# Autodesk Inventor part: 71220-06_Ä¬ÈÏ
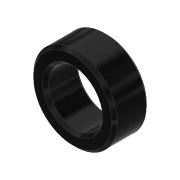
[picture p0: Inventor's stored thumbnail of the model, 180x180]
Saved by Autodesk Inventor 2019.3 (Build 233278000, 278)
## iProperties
Created: 2010-06
Part Number: 71220-06_Ä¬ÈÏ
Material: Ogólny
Document SubType Name: Modeling
Designer: CADENGINEERING4
Density: 1 g/cm^3
Appearance: Gładki — czarny
Author: CADENGINEERING4
Revision Number: ÈÎºÎ
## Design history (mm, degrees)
feature "NONE"
node "Bryła1"
